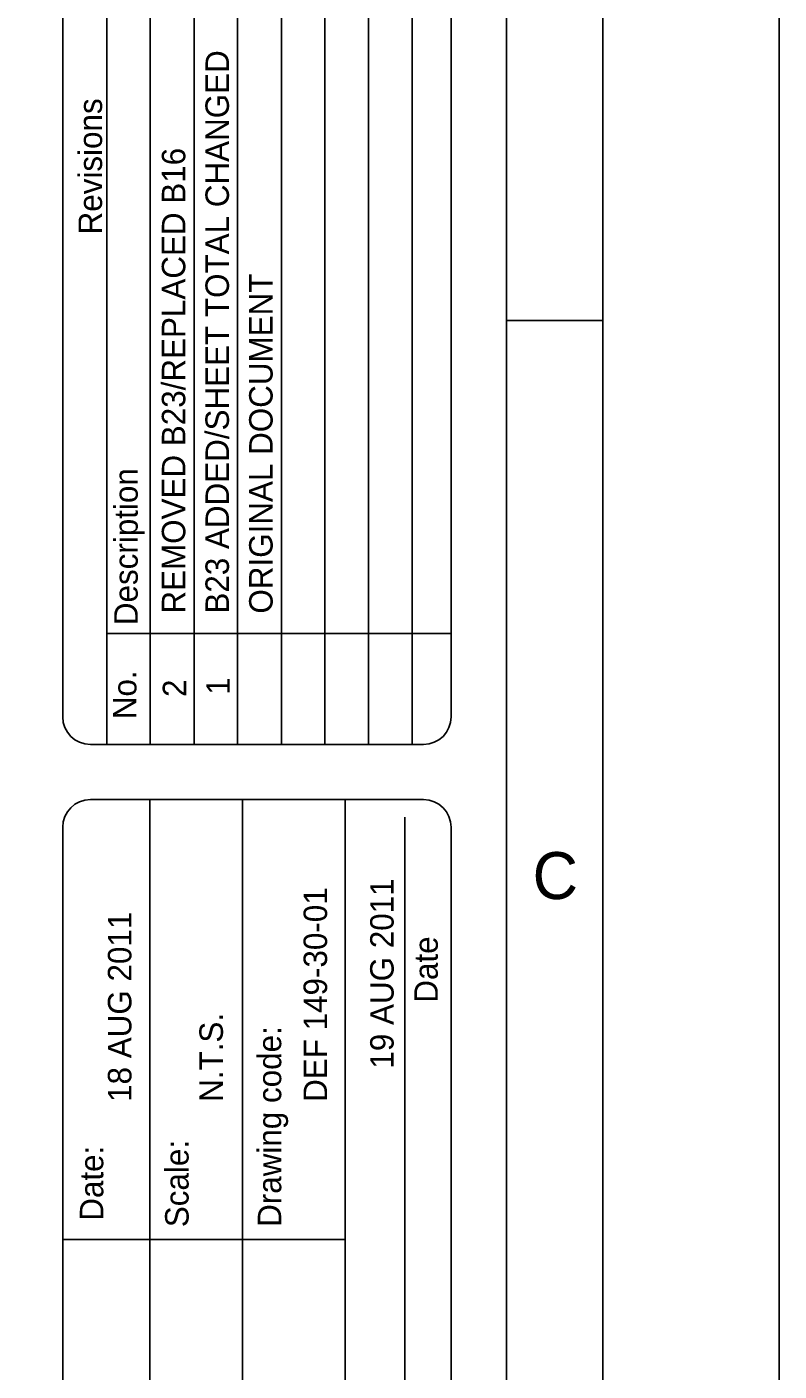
# Model space of a CAD drawing. Extents: x -0.04 to 2.79, y -0.02 to 1.81.
# Drawn here: x 2.5249 to 2.7917, y 0.9292 to 1.4065 of the extents above; entities that cross this region are included whole.
import ezdxf

# ---------------------------------------------------------------- set-up
doc = ezdxf.new("R2010")
doc.units = 0
for name, color, linetype in [('G-ANNO-NPLT', 7, 'Continuous'), ('G-ANNO-PLOT', 7, 'Continuous'), ('G-ANNO-TTLB', 7, 'Continuous')]:
    doc.layers.add(name, color=color, linetype=linetype)

msp = doc.modelspace()

# ---------------------------------------------------------------- linework, layer by layer
at = {"layer": 'G-ANNO-NPLT'}
msp.add_lwpolyline([(-0.04167, 1.8125), (2.79167, 1.8125), (2.79167, -0.02083), (-0.04167, -0.02083)], close=True, dxfattribs=at)
at = {"layer": 'G-ANNO-PLOT'}
msp.add_line((2.79167, 1.8125), (2.79167, -0.02083), dxfattribs=at)
msp.add_lwpolyline([(0, 0), (2.79167, 0), (2.79167, 1.79167), (0, 1.79167)], close=True, dxfattribs=at)
at = {"layer": 'G-ANNO-TTLB'}
for p, q in [((2.55319, 1.55567), (2.55319, 1.15168)), ((2.56861, 1.55567), (2.56861, 1.15168)), ((2.58415, 1.55567), (2.58415, 1.15168)), ((2.59962, 1.55567), (2.59962, 1.15168)), ((2.61512, 1.55567), (2.61512, 1.15168)), ((2.63058, 1.55567), (2.63058, 1.15168)), ((2.646, 1.55567), (2.646, 1.15168)), ((2.66154, 1.55567), (2.66154, 1.15168)), ((2.69501, 1.30222), (2.72917, 1.30222)), ((2.55319, 1.19107), (2.67536, 1.19107)), ((2.56849, 1.13212), (2.56849, 0.97595)), ((2.60138, 1.13212), (2.60138, 0.97595)), ((2.63771, 1.13212), (2.63771, 0.78365)), ((2.65896, 0.78952), (2.65896, 1.12584)), ((2.63771, 0.97595), (2.53757, 0.97595)), ((2.56849, 0.97595), (2.56849, 0.78365)), ((2.60138, 0.97595), (2.60138, 0.78365))]:
    msp.add_line(p, q, dxfattribs=at)
for points in [[(0.08333, 0.04167), (2.72917, 0.04167), (2.72917, 1.75), (0.2515, 1.75)], [(0.11656, 0.08028), (2.69501, 0.08028), (2.69501, 1.71305), (0.11656, 1.71305)], [(2.53757, 1.54583), (2.53757, 1.16152)], [(2.67536, 1.16152), (2.67536, 1.54583)], [(2.54741, 1.1517), (2.66552, 1.1517)], [(2.66552, 1.13212), (2.54741, 1.13212)], [(2.53757, 1.12228), (2.53757, 0.53206)], [(2.67536, 0.53191), (2.67536, 1.12228)]]:
    msp.add_lwpolyline(points, dxfattribs=at)
for centre, major_axis, start_param, end_param in [((2.54741, 1.16152), (-0.00984, 0), 0, 1.570796), ((2.66552, 1.16152), (0.00984, 0), 4.712389, 6.283185), ((2.5474, 1.12228), (-0.00984, 0), 4.712389, 6.283185), ((2.66552, 1.12228), (-0.00984, 0), 3.141593, 4.712389)]:
    msp.add_ellipse(centre, major_axis=major_axis, ratio=0.999936, start_param=start_param, end_param=end_param, dxfattribs=at)

# ---------------------------------------------------------------- texts
for s, height, p in [('B23 ADDED/SHEET TOTAL CHANGED', 0.0083333, (2.59653, 1.19815)), ('Revisions', 0.008333, (2.55152, 1.33278)), ('REMOVED B23/REPLACED B16', 0.0083333, (2.58106, 1.19815)), ('ORIGINAL DOCUMENT', 0.0083333, (2.61203, 1.19815)), ('Description', 0.0083333, (2.56418, 1.19405)), ('No.', 0.008333, (2.56372, 1.16065)), ('2', 0.00833, (2.58138, 1.16855)), ('1', 0.00833, (2.59684, 1.16931)), ('19 AUG 2011', 0.0083333, (2.65496, 1.03661)), ('DEF 149-30-01', 0.0083333, (2.63134, 1.02479)), ('18 AUG 2011', 0.0083333, (2.56194, 1.02479)), ('Submitted by:                                                                 Date', 0.0083333, (2.67061, 0.79063)), ('N.T.S.', 0.008333, (2.5944, 1.02479)), ('Drawing code:', 0.0083333, (2.61508, 0.98042)), ('Date:', 0.008333, (2.55197, 0.98259)), ('Scale:', 0.008333, (2.58223, 0.9803))]:
    msp.add_text(s, height=height, rotation=90, dxfattribs=at).set_placement(p)
msp.add_text('C', height=0.01667, dxfattribs=at).set_placement((2.70424, 1.0968))

doc.saveas('drawing.dxf')
